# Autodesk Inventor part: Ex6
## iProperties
Author: Administrator
Created: 2001-01
Part Number: Ex6
Material: Default
Document SubType Name: Sheet Metal
Designer: Administrator
Control State: 0
Master: False
Checked Out: False
PropertySet Name: Design Tracking Control
Shininess: 20.0
PropertySet Name: _Private Model Information
Density: 0.0
Volumn: 0.0
Area: 0.0
PropertySet Name: Model Information
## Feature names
1. Cut1
2. Hole1
3. Corner Chamfer1
4. Corner Chamfer2
5. Plate1
6. Plate2
7. Bend1
8. Plate3
9. Bend2
